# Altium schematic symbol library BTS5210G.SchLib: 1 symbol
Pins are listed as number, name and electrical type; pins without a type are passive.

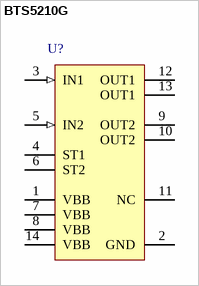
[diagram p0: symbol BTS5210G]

## BTS5210G
designator U?
Smart High-Side Power Switch PROFET, 2 Channels, 1.7 A Load Current, -40 to 150 degC, PG-DSO-14-37, Reel, Green; Manufacturer: Infineon; PartNumber: BTS5210G; Channels: 2; Green: TRUE; Group: Automotive Qualified; Load Current (typ): 1.7 A; Ptot (max): 3.05 W; Recommended Operating Voltage Max.: 40 V; Recommended Operating Voltage Min.: 5.5 V; RON @ 25degreesC: 140 mOhm; RON(max) @ 150degreesC: 280 mOhm; toff (max): 270 us; ton (max): 250 us
footprint INF-PG-DSO-14-37_N (SOP, 14-Leads, Body 8.65x3.9mm, Pitch 1.27mm, IPC Medium Density)
footprint INF-PG-DSO-14-37_L (SOP, 14-Leads, Body 8.65x3.9mm, Pitch 1.27mm, IPC High Density)
footprint INF-PG-DSO-14-37_M (SOP, 14-Leads, Body 8.65x3.9mm, Pitch 1.27mm, IPC Low Density)
pins: 1 VBB (power) "Positive power supply voltage. Design the wiring for the simultaneous max. short circuit currents from channel 1 to 2 and also for low thermal resistance", 2 GND (power) "Logic Ground", 3 IN1 (in) "Input 1,2 activates channel 1,2 in case of logic high signal", 4 ST1 (oc) "Diagnostic feedback 1,2 of channel 1,2 open drain", 5 IN2 (in) "Input 1,2 activates channel 1,2 in case of logic high signal", 6 ST2 (oc) "Diagnostic feedback 1,2 of channel 1,2 open drain", 7 VBB (power) "Positive power supply voltage. Design the wiring for the simultaneous max. short circuit currents from channel 1 to 2 and also for low thermal resistance", 8 VBB (power) "Positive power supply voltage. Design the wiring for the simultaneous max. short circuit currents from channel 1 to 2 and also for low thermal resistance", 9 OUT2 (power) "Output 1,2 protected high-side power output of channel 1,2. Design the wiring for the max. short circuit current; both output pins have to be connected in parallel for operation according this spec.", 10 OUT2 (power) "Output 1,2 protected high-side power output of channel 1,2. Design the wiring for the max. short circuit current; both output pins have to be connected in parallel for operation according this spec.", 11 NC "Not Connected", 12 OUT1 (power) "Output 1,2 protected high-side power output of channel 1,2. Design the wiring for the max. short circuit current; both output pins have to be connected in parallel for operation according this spec.", 13 OUT1 (power) "Output 1,2 protected high-side power output of channel 1,2. Design the wiring for the max. short circuit current; both output pins have to be connected in parallel for operation according this spec.", 14 VBB (power) "Positive power supply voltage. Design the wiring for the simultaneous max. short circuit currents from channel 1 to 2 and also for low thermal resistance"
